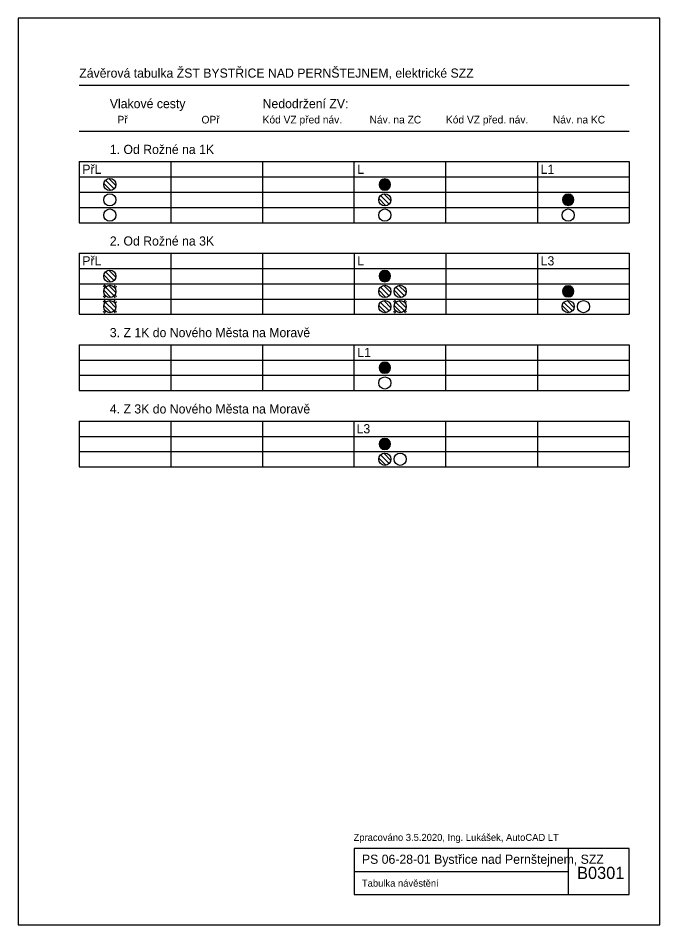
# Model space of a CAD drawing. Extents: x -591 to 5777, y 380 to 2087.
# Drawn here: x 420 to 630, y 380 to 677 of the extents above; entities that cross this region are included whole.
import ezdxf

# ---------------------------------------------------------------- set-up
doc = ezdxf.new("R2010")
doc.units = 0
for name, color, linetype in [('0B', 7, 'Continuous'), ('Implicitní', 7, 'Continuous'), ('Vrstva 63', 7, 'Continuous')]:
    doc.layers.add(name, color=color, linetype=linetype)

# ---------------------------------------------------------------- blocks, each defined once
blk = doc.blocks.new('ZT75')
at = {"layer": 'Implicitní'}
for points in [[(-18.1, 3.2), (18.1, 3.2)], [(-17.6, 0.7), (17.6, 0.7)], [(-17.3, 6.4), (17.3, 6.4)], [(-15.7, 9.6), (15.7, 9.6)], [(-14, 12), (14, 12)], [(-12.4, 13.6), (12.4, 13.6)], [(-10.4, 15.2), (10.4, 15.2)], [(-7.6, 16.8), (7.6, 16.8)], [(-18.1, -3.2), (18.1, -3.2)], [(-17.6, -0.7), (17.6, -0.7)], [(-17.3, -6.4), (17.3, -6.4)], [(-15.7, -9.6), (15.7, -9.6)], [(-14, -12), (14, -12)], [(-12.4, -13.6), (12.4, -13.6)], [(-10.4, -15.2), (10.4, -15.2)], [(-7.6, -16.8), (7.6, -16.8)]]:
    blk.add_lwpolyline(points, dxfattribs=at)
for start, end in [(0, 180), (180, 0)]:
    blk.add_arc((0, 0), 18.4, start, end, dxfattribs=at)
blk = doc.blocks.new('ZT76')
at = {"layer": 'Implicitní'}
for p, q in [((3.7, 19.7), (-19.7, -3.7)), ((14.1, 14.1), (-14.1, -14.1)), ((19.7, 3.7), (-3.7, -19.7))]:
    blk.add_line(p, q, dxfattribs=at)
blk.add_circle((0, 0), 20, dxfattribs=at)
blk = doc.blocks.new('ZT74')
at = {"layer": 'Implicitní'}
blk.add_circle((0, 0), 20, dxfattribs=at)
blk = doc.blocks.new('ZT78')
at = {"layer": 'Implicitní'}
for p, q in [((-30.7, 25.7), (-22.7, 17.7)), ((-25.7, 30.7), (-17.7, 22.7)), ((17.5, 21.7), (25.5, 29.7)), ((22.5, 16.7), (30.5, 24.7)), ((-31.3, -25.5), (-23.3, -17.5)), ((-26.3, -30.5), (-18.3, -22.5)), ((17.5, -21.7), (25.5, -29.7)), ((22.5, -16.7), (30.5, -24.7))]:
    blk.add_line(p, q, dxfattribs=at)

msp = doc.modelspace()

# ---------------------------------------------------------------- linework, layer by layer
at = {"layer": '0B'}
for p, q in [((440, 655), (620, 655)), ((440, 640), (620, 640)), ((440, 630), (620, 630)), ((440, 630), (440, 610)), ((470, 630), (470, 610)), ((500, 630), (500, 610)), ((530, 610), (530, 630)), ((560, 610), (560, 630)), ((590, 630), (590, 610)), ((620, 630), (620, 610)), ((440, 625), (620, 625)), ((440, 620), (620, 620)), ((440, 615), (620, 615)), ((440, 615), (620, 615)), ((440, 610), (620, 610)), ((440, 600), (620, 600)), ((440, 600), (440, 580)), ((470, 600), (470, 580)), ((500, 600), (500, 580)), ((530, 600), (530, 580)), ((560, 600), (560, 580)), ((590, 600), (590, 580)), ((620, 600), (620, 580)), ((440, 595), (620, 595)), ((440, 595), (620, 595)), ((440, 590), (620, 590)), ((440, 585), (620, 585)), ((440, 585), (620, 585)), ((440, 580), (620, 580)), ((440, 580), (620, 580)), ((440, 580), (620, 580)), ((440, 570), (620, 570)), ((440, 570), (440, 555)), ((470, 570), (470, 555)), ((500, 570), (500, 555)), ((530, 555), (530, 570)), ((560, 555), (560, 570)), ((590, 570), (590, 555)), ((620, 570), (620, 555)), ((440, 565), (620, 565)), ((440, 560), (620, 560)), ((440, 555), (620, 555)), ((440, 555), (620, 555)), ((440, 545), (620, 545)), ((440, 545), (440, 530)), ((470, 545), (470, 530)), ((500, 545), (500, 530)), ((530, 530), (530, 545)), ((560, 530), (560, 545)), ((590, 545), (590, 530)), ((620, 545), (620, 530)), ((440, 540), (620, 540)), ((440, 535), (620, 535)), ((440, 530), (620, 530)), ((440, 530), (620, 530)), ((620, 405), (530, 405)), ((530, 405), (530, 390)), ((600, 405), (600, 390)), ((620, 390), (620, 405)), ((530, 397.5), (600, 397.5)), ((530, 390), (620, 390))]:
    msp.add_line(p, q, dxfattribs=at)
at = {"layer": 'Vrstva 63'}
msp.add_lwpolyline([(420, 380), (630, 380), (630, 677), (420, 677)], close=True, dxfattribs=at)

# ---------------------------------------------------------------- block references
at = {"layer": '0B'}
for name, p, xscale, yscale, rotation in [('ZT76', (450, 622.5), 0.10000000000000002, 0.1, 89.99999999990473), ('ZT75', (540, 622.5), 0.1, 0.10000000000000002, -9.526953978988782e-11), ('ZT74', (450, 617.5), 0.1, 0.10000000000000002, -9.526953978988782e-11), ('ZT76', (540, 617.5), 0.10000000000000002, 0.1, 89.99999999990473), ('ZT75', (600, 617.5), 0.1, 0.10000000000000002, -9.526953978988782e-11), ('ZT74', (450, 612.5), 0.1, 0.10000000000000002, -9.526953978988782e-11), ('ZT74', (540, 612.5), 0.1, 0.10000000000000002, -9.526953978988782e-11), ('ZT74', (600, 612.5), 0.1, 0.10000000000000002, -9.526953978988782e-11), ('ZT76', (450, 592.5), 0.10000000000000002, 0.10000000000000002, 89.99999999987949), ('ZT75', (540, 592.5), 0.1, 0.10000000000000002, -1.2050326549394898e-10), ('ZT78', (450, 587.5), 0.06999999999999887, 0.06999999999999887, -1.2050326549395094e-10), ('ZT76', (450, 587.5), 0.10000000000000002, 0.10000000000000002, 89.99999999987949), ('ZT76', (540, 587.5), 0.10000000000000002, 0.10000000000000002, 89.99999999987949), ('ZT76', (545, 587.5), 0.10000000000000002, 0.10000000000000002, 89.99999999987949), ('ZT76', (545, 587.5), 0.10000000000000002, 0.10000000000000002, 89.99999999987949), ('ZT75', (600, 587.5), 0.1, 0.10000000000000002, -1.2050326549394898e-10), ('ZT78', (450, 582.5), 0.06999999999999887, 0.06999999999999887, -1.2050326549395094e-10), ('ZT76', (450, 582.5), 0.10000000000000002, 0.10000000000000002, 89.99999999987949), ('ZT76', (540, 582.5), 0.10000000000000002, 0.10000000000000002, 89.99999999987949), ('ZT78', (545, 582.5), 0.06999999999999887, 0.06999999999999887, -1.2050326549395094e-10), ('ZT76', (545, 582.5), 0.10000000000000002, 0.10000000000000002, 89.99999999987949), ('ZT76', (545, 582.5), 0.10000000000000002, 0.10000000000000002, 89.99999999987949), ('ZT76', (600, 582.5), 0.10000000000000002, 0.10000000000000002, 89.99999999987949), ('ZT74', (605, 582.5), 0.1, 0.10000000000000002, -1.2050326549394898e-10), ('ZT75', (540, 562.5), 0.1, 0.10000000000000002, -1.2050326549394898e-10), ('ZT74', (540, 557.5), 0.1, 0.10000000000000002, -1.2050326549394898e-10), ('ZT75', (540, 537.5), 0.1, 0.10000000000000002, -1.2050326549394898e-10), ('ZT76', (540, 532.5), 0.10000000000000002, 0.10000000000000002, 89.99999999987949), ('ZT74', (545, 532.5), 0.1, 0.10000000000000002, -1.2050326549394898e-10)]:
    msp.add_blockref(name, p, dxfattribs=dict(at, xscale=xscale, yscale=yscale, rotation=rotation))

# ---------------------------------------------------------------- texts
for s, height, p in [('Závěrová tabulka ŽST BYSTŘICE NAD PERNŠTEJNEM, elektrické SZZ', 3, (440, 657.5)), ('Vlakové cesty', 3, (450, 647.5)), ('Nedodržení ZV:', 3, (500, 647.5)), ('Př', 2.5, (452.5, 642.5)), ('OPř', 2.5, (480, 642.5)), ('Kód VZ před náv.', 2.5, (500, 642.5)), ('Náv. na ZC', 2.5, (535, 642.5)), ('Kód VZ před. náv.', 2.5, (560, 642.5)), ('Náv. na KC', 2.5, (595, 642.5)), ('1. Od Rožné na 1K', 3, (450, 632.5)), ('PřL', 3, (441, 626)), ('L', 3, (531, 626)), ('L1', 3, (591, 626)), ('2. Od Rožné na 3K', 3, (450, 602.5)), ('PřL', 3, (441, 596)), ('L', 3, (531, 596)), ('L3', 3, (591, 596)), ('3. Z 1K do Nového Města na Moravě', 3, (450, 572.5)), ('L1', 3, (531, 566)), ('4. Z 3K do Nového Města na Moravě', 3, (450, 547.5)), ('L3', 3, (530.75, 541)), ('Zpracováno 3.5.2020, Ing. Lukášek, AutoCAD LT', 2.2988, (529.77, 407.5)), ('PS 06-28-01 Bystřice nad Pernštejnem, SZZ', 3, (532.5, 400)), ('B0301', 4, (602.92, 395.02)), ('Tabulka návěstění', 2.3, (532.5, 392.5))]:
    msp.add_text(s, height=height, rotation=360, dxfattribs=at).set_placement(p)

doc.saveas('drawing.dxf')
